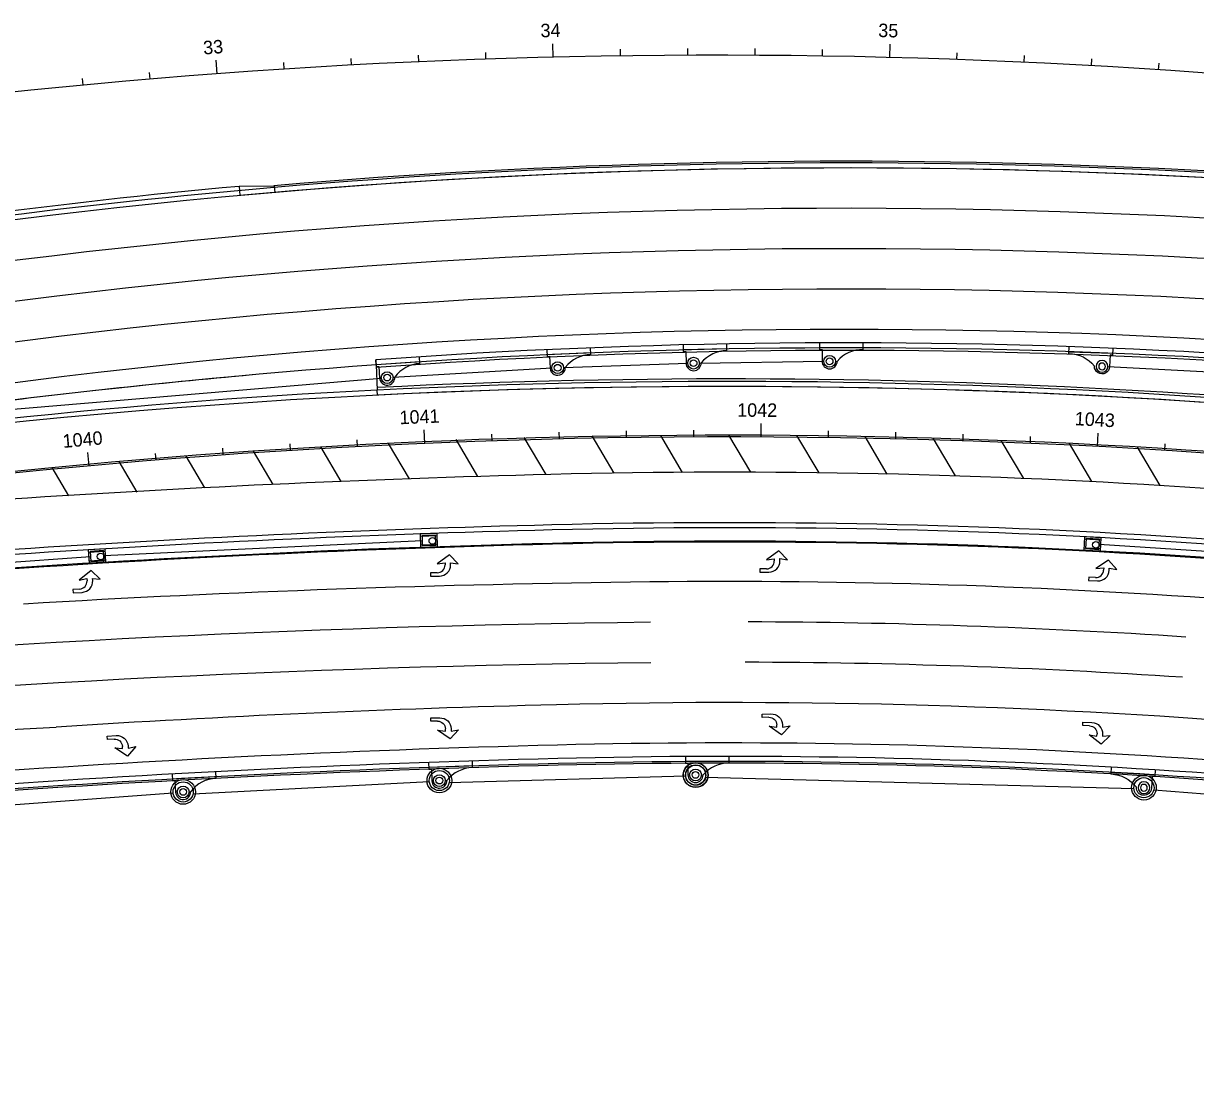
# Model space of a CAD drawing. Extents: x 468143 to 491361, y 1438528 to 1468730.
# Drawn here: x 486331.8 to 486680.1, y 1467283.2 to 1467597.2 of the extents above; entities that cross this region are included whole.
import ezdxf

# ---------------------------------------------------------------- set-up
doc = ezdxf.new("R2010")
doc.units = 0
doc.layers.add('Default', color=7, linetype='Continuous')
doc.layers.add('Xreference_dp', color=7, linetype='Continuous')

# ---------------------------------------------------------------- blocks, each defined once
blk = doc.blocks.new('POINT_DISPLAY')
at = {"layer": 'Default'}
blk.add_line((0, 0), (0, 0), dxfattribs=at)
blk = doc.blocks.new('InltCurb1_35')
at = {"layer": 'Default'}
for p, q in [((2.25, 2), (2.25, 5.5)), ((-10, 2), (-10, 0)), ((-10, 1.5), (3, 1.5)), ((3, 2), (2.25, 2)), ((3, 0), (3, 2))]:
    blk.add_line(p, q, dxfattribs=at)
for radius in [1.75, 1]:
    blk.add_circle((0, 5.5), radius, dxfattribs=at)
for centre, radius, start, end in [((0, 5.5), 2.25, 0, 180), ((-9.85, 12), 10, 269.1432, 319.4677)]:
    blk.add_arc(centre, radius, start, end, dxfattribs=at)
for p in [(-0.66, 7.12), (0, 7.75), (0, 7.25), (0, 7.25), (0.7, 7.1), (-1.75, 5.5), (-1.75, 5.5), (-1.62, 4.84), (-1.6, 6.2), (-1.26, 4.28), (-1.22, 6.76), (-0.7, 3.9), (0, 5.5), (0, 5.5), (0, 3.75), (0, 3.75), (0.66, 3.88), (1.22, 4.24), (1.26, 6.72), (1.6, 4.8), (1.62, 6.16), (1.75, 5.5), (1.75, 5.5), (0, 0), (0, 0)]:
    blk.add_blockref('POINT_DISPLAY', p, dxfattribs=at)
blk = doc.blocks.new('InltCurb7_40')
at = {"layer": 'Default'}
for p, q in [((2.5, 4), (-2.5, 4)), ((-2.5, 4), (-2.5, 0)), ((2.5, 0), (2.5, 4)), ((2.5, 3.25), (-2.5, 3.25)), ((-2.5, 0.75), (2.5, 0.75)), ((-2.5, 0), (2.5, 0))]:
    blk.add_line(p, q, dxfattribs=at)
blk.add_lwpolyline([(-2, 0.5), (2, 0.5), (2, 3.5), (-2, 3.5)], close=True, dxfattribs=at)
blk.add_circle((-1.04, 2.19), 1, dxfattribs=at)
for p in [(-2, 3.5), (0, 4), (0, 3.5), (0, 3.5), (2, 3.5), (-2, 2), (-2, 2), (-2, 0.5), (0, 2), (0, 2), (0, 0.5), (0, 0.5), (0, 0), (0, 0), (2, 2), (2, 2), (2, 0.5)]:
    blk.add_blockref('POINT_DISPLAY', p, dxfattribs=at)
blk = doc.blocks.new('JBottom60Dia')
at = {"layer": 'Default'}
for radius in [3.67, 3, 3]:
    blk.add_circle((0, 0), radius, dxfattribs=at)
for p in [(-2.75, 1.21), (-2.09, 2.15), (-1.13, 2.78), (0, 3), (0, 3), (0, 3), (0, 0), (0, 0), (0, 0), (1.21, 2.75), (2.15, 2.09), (2.78, 1.13), (3, 0), (3, 0), (-3, 0), (-3, 0), (-2.78, -1.13), (-2.15, -2.09), (-1.21, -2.75), (0, -3), (0, -3), (0, -3), (1.13, -2.78), (2.09, -2.15), (2.75, -1.21)]:
    blk.add_blockref('POINT_DISPLAY', p, dxfattribs=at)
blk = doc.blocks.new('DALeftTurn_1')
at = {"layer": 'Default'}
for points in [[(5.67, 3.17), (2, 0.5), (4.33, 0.83), (4.33, 0.17)], [(6, 0.17), (6, 0.83), (8.25, 0.5), (5.67, 3.17)], [(2, -2.17), (0, -2.17), (0, -3.17), (2.67, -3.17)]]:
    blk.add_lwpolyline(points, dxfattribs=at)
for centre, radius in [((2, 0.17), 2.33), ((2.67, 0.17), 3.33)]:
    blk.add_arc(centre, radius, 270, 0, dxfattribs=at)

msp = doc.modelspace()

# ---------------------------------------------------------------- linework, layer by layer
at = {"layer": 'Xreference_dp'}
for p, q in [((486489.23, 1467587.19), (486489.13, 1467591.19)), ((486509.23, 1467587.58), (486509.2, 1467589.58)), ((486529.23, 1467587.76), (486529.22, 1467589.76)), ((486549.23, 1467587.75), (486549.24, 1467589.75)), ((486569.22, 1467587.53), (486569.26, 1467589.53)), ((486589.22, 1467587.12), (486589.32, 1467591.12)), ((486389.36, 1467582.28), (486389.07, 1467586.27)), ((486409.31, 1467583.66), (486409.19, 1467585.66)), ((486429.28, 1467584.84), (486429.17, 1467586.84)), ((486449.25, 1467585.83), (486449.17, 1467587.82)), ((486469.24, 1467586.61), (486469.17, 1467588.61)), ((486609.21, 1467586.5), (486609.28, 1467588.5)), ((486629.19, 1467585.69), (486629.29, 1467587.69)), ((486649.17, 1467584.68), (486649.28, 1467586.67)), ((486369.42, 1467580.7), (486369.26, 1467582.69)), ((486669.13, 1467583.46), (486669.26, 1467585.46)), ((486349.5, 1467578.92), (486349.32, 1467580.91)), ((486395.86, 1467548.8), (486406.24, 1467548.97)), ((486395.86, 1467548.8), (486396.11, 1467546.06)), ((486406.28, 1467548.97), (486406.45, 1467546.98)), ((486436.58, 1467495.7), (486436.5, 1467497.2)), ((486436.58, 1467495.7), (486436.95, 1467488.21)), ((486492.3, 1467494.93), (486529.19, 1467496.19)), ((486532.69, 1467496.26), (486569.62, 1467496.76)), ((486654.08, 1467495.19), (486701.06, 1467492.71)), ((486311.43, 1467481.03), (486438.13, 1467491.8)), ((486441.62, 1467492.04), (486488.8, 1467494.78)), ((486437.02, 1467486.71), (486436.95, 1467488.21)), ((486551.05, 1467474.26), (486551.07, 1467478.26)), ((486451.08, 1467472.34), (486450.9, 1467476.34)), ((486471.06, 1467473.11), (486471, 1467475.11)), ((486487.12, 1467463.08), (486480.57, 1467474.15)), ((486491.05, 1467473.68), (486491.01, 1467475.68)), ((486507.39, 1467463.51), (486500.8, 1467474.64)), ((486511.05, 1467474.06), (486511.02, 1467476.06)), ((486527.67, 1467463.74), (486521.19, 1467474.69)), ((486531.05, 1467474.26), (486531.04, 1467476.26)), ((486547.94, 1467463.77), (486541.43, 1467474.78)), ((486568.22, 1467463.61), (486561.67, 1467474.68)), ((486571.05, 1467474.07), (486571.08, 1467476.07)), ((486588.5, 1467463.25), (486581.91, 1467474.39)), ((486591.04, 1467473.69), (486591.09, 1467475.69)), ((486611.04, 1467473.12), (486611.1, 1467475.12)), ((486631.02, 1467472.36), (486631.11, 1467474.36)), ((486651, 1467471.42), (486651.21, 1467475.41)), ((486391.18, 1467468.91), (486391.03, 1467470.91)), ((486411.13, 1467470.24), (486411.01, 1467472.24)), ((486426.26, 1467461.05), (486420.2, 1467471.29)), ((486431.1, 1467471.39), (486430.99, 1467473.39)), ((486446.55, 1467461.83), (486440.32, 1467472.35)), ((486466.84, 1467462.51), (486460.35, 1467473.47)), ((486608.78, 1467462.69), (486602.15, 1467473.9)), ((486629.06, 1467461.94), (486622.38, 1467473.22)), ((486649.33, 1467460.99), (486642.61, 1467472.34)), ((486669.59, 1467459.84), (486662.83, 1467471.26)), ((486670.97, 1467470.28), (486671.09, 1467472.27)), ((486351.31, 1467465.67), (486350.95, 1467469.65)), ((486371.24, 1467467.39), (486371.07, 1467469.38)), ((486385.72, 1467459.17), (486380.14, 1467468.59)), ((486405.99, 1467460.16), (486400.14, 1467470.03)), ((486345.25, 1467456.8), (486340.31, 1467465.14)), ((486365.59, 1467457.85), (486360.2, 1467466.96)), ((486355.68, 1467438.98), (486450.28, 1467443.47)), ((486651.48, 1467442.35), (486696.7, 1467439.45)), ((486278.67, 1467433.43), (486351.69, 1467438.74)), ((486261.71, 1467383.58), (486341.48, 1467388)), ((486528.54, 1467373.43), (486458.32, 1467371.46)), ((486452.41, 1467371.75), (486382.19, 1467368.09)), ((486661.8, 1467369.59), (486534.42, 1467372.98)), ((486376.27, 1467368.36), (486315.74, 1467363.89)), ((486718.76, 1467365.25), (486667.67, 1467369.19))]:
    msp.add_line(p, q, dxfattribs=at)
for centre, radius, start, end in [((486537.7, 1465584.94), 2002.84, 65.37329, 99.90546), ((486576.17, 1465574.26), 1982, 80.60151, 94.91832), ((486576.17, 1465574.26), 1981.5, 80.60151, 94.91867), ((486576.17, 1465574.26), 1980, 80.60151, 99.90595), ((486576.17, 1465574.26), 1980, 80.59384, 95.2178), ((486576.17, 1465574.26), 1982.75, 95.2178, 99.90595), ((486576.17, 1465574.26), 1981.5, 94.91867, 99.90595), ((486576.17, 1465574.26), 1968, 80.60151, 99.90595), ((486576.17, 1465574.26), 1956, 80.60151, 99.90595), ((486576.17, 1465574.26), 1944, 80.59814, 99.90595), ((486576.17, 1465574.26), 1932, 80.72286, 99.90595), ((486576.17, 1465574.26), 1928, 79.86924, 94.15426), ((486576.17, 1465574.26), 1926.5, 79.87546, 94.1553), ((486576.17, 1465574.26), 1925.75, 80.19274, 94.15581), ((486597.77, 1465276.99), 2224.56, 94.1553, 99.90595), ((486597.77, 1465276.99), 2224.56, 95.10723, 97.2853), ((486531.6, 1465570.76), 1919.78, 92.82593, 99.95282), ((486541.29, 1465374.28), 2115, 79.49165, 99.02499), ((486541.29, 1465374.28), 2117.25, 80.18456, 92.82593), ((486541.29, 1465374.28), 2116.5, 79.49165, 92.82593), ((486541.29, 1465374.28), 2115, 79.49165, 92.82593), ((486541.29, 1465374.28), 2100, 65.36712, 99.90595), ((486541.29, 1465374.28), 2100.5, 80.78193, 95.46596), ((486541.29, 1465374.28), 2100.5, 95.46596, 99.90595), ((486541.29, 1465374.28), 2089.5, 80.77624, 91.44817), ((486587.77, 1463535.87), 3928.5, 91.44817, 93.86982), ((486587.77, 1463535.87), 3913.5, 91.44817, 93.86982), ((486587.77, 1463535.87), 3912, 91.44817, 93.86982), ((486541.29, 1465374.28), 2074.5, 80.77953, 91.44817), ((486541.29, 1465374.28), 2073, 80.77655, 91.44817), ((486541.29, 1465374.28), 2069, 80.77607, 91.44817), ((486541.29, 1465374.28), 2068.75, 80.77607, 91.44817), ((486587.77, 1463535.87), 3908, 91.44817, 94.29909), ((486587.77, 1463535.87), 3907.75, 91.44817, 94.17965), ((486562.18, 1463531.4), 3900, 90.64932, 93.38667), ((486541.29, 1465374.28), 2057, 80.77607, 90.64932), ((486562.18, 1463531.4), 3888, 90.64932, 99.90595), ((486541.29, 1465374.28), 2045, 86.18942, 89.83493), ((486562.18, 1463531.4), 3876, 90.64932, 99.90595), ((486541.29, 1465374.28), 2033, 86.19453, 89.85859), ((486587.77, 1463535.87), 3860, 91.44817, 93.65823), ((486541.29, 1465374.28), 2021, 78.93045, 91.44817), ((486587.77, 1463535.87), 3848, 91.44817, 94.24896), ((486541.29, 1465374.28), 2009, 81.45128, 91.44817), ((486587.77, 1463535.87), 3842, 91.44817, 94.26097), ((486587.77, 1463535.87), 3842.5, 91.44817, 94.25997), ((486587.77, 1463535.87), 3844, 91.44817, 94.25697), ((486541.29, 1465374.28), 2005, 81.30471, 91.44817), ((486541.29, 1465374.28), 2003.5, 81.23483, 91.44817), ((486541.29, 1465374.28), 2003, 81.20431, 91.44817)]:
    msp.add_arc(centre, radius, start, end, dxfattribs=at)

# ---------------------------------------------------------------- block references
for name, p, rotation in [('InltCurb1_35', (486571.37, 1467502.26), 179.99167229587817), ('InltCurb1_35', (486490.32, 1467500.35), -177.59932508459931), ('InltCurb1_35', (486530.82, 1467501.72), -178.76431210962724), ('InltCurb1_35', (486439.5, 1467497.41), -176.03809449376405), ('InltCurb7_40', (486452.23, 1467445.52), -178.51796813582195), ('InltCurb7_40', (486649.59, 1467444.45), 177.0400403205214), ('InltCurb7_40', (486353.56, 1467440.85), -176.54939443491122), ('DALeftTurn_1', (486550.6, 1467437.19), 0.5650560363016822), ('DALeftTurn_1', (486452.74, 1467436.07), -0.1730460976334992), ('DALeftTurn_1', (486648.46, 1467434.73), -2.601842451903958), ('DALeftTurn_1', (486346.38, 1467431.09), 2.8277836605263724), ('InltCurb1_35', (486455.2, 1467377.58), -178.00051645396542), ('JBottom60Dia', (486531.53, 1467373.76), 75.04782274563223), ('JBottom60Dia', (486531.59, 1467373.69), 75.04782274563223), ('InltCurb1_35', (486531.51, 1467379.26), -179.86340224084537), ('JBottom60Dia', (486379.25, 1467368.71), 75.04782274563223), ('InltCurb1_35', (486378.95, 1467374.2), -176.86145427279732), ('JBottom60Dia', (486455.39, 1467372.09), 75.04782274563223), ('JBottom60Dia', (486664.77, 1467369.97), 75.04782274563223)]:
    msp.add_blockref(name, p, dxfattribs=dict(at, rotation=rotation))
for name, p, yscale, rotation in [('InltCurb1_35', (486652.53, 1467500.75), -1.0000000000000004, -2.1213116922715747), ('DALeftTurn_1', (486452.86, 1467387.57), -1, 0.5953034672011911), ('DALeftTurn_1', (486551.35, 1467388.7), -1.0000000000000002, 1.3334056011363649), ('DALeftTurn_1', (486646.52, 1467386.28), -1, -1.833492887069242), ('DALeftTurn_1', (486356.88, 1467382.16), -1.0000000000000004, 3.5961332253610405), ('InltCurb1_35', (486665.1, 1467375.46), -1.0000000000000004, -3.3971455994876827)]:
    msp.add_blockref(name, p, dxfattribs=dict(at, yscale=yscale, rotation=rotation))

# ---------------------------------------------------------------- texts
for s, rotation, p in [('34', 1.3868, (486485.5, 1467593.11)), ('35', 358.526, (486585.78, 1467593.21)), ('33', 4.2475, (486385.34, 1467588)), ('1041', 2.4622, (486443.64, 1467478.03)), ('1042', 359.7339, (486543.89, 1467480.29)), ('1043', 357.0055, (486644.14, 1467477.78)), ('1040', 5.1906, (486343.61, 1467471))]:
    msp.add_text(s, height=4, rotation=rotation, dxfattribs=at).set_placement(p)

doc.saveas('drawing.dxf')
